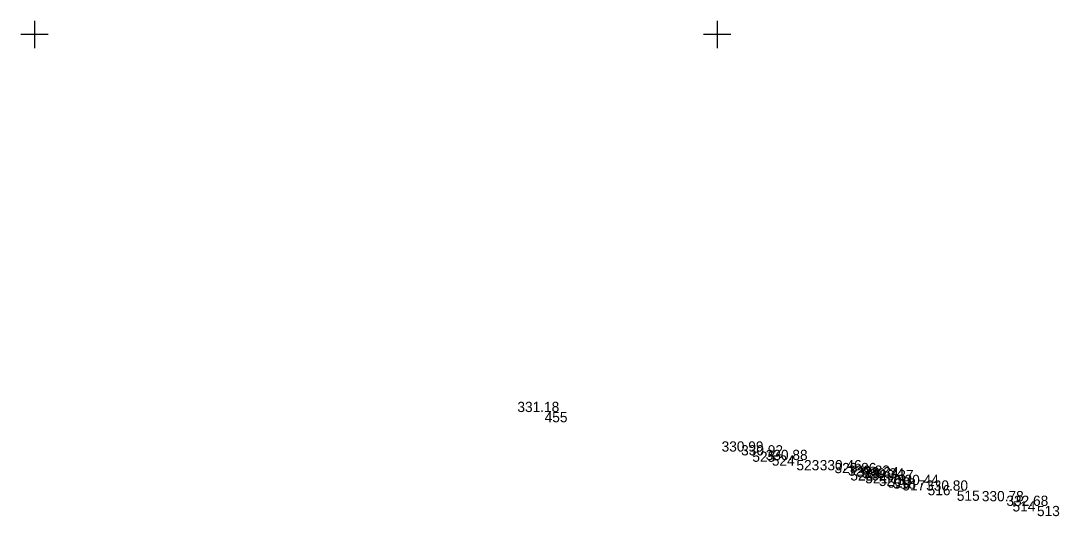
# Model space of a CAD drawing. Extents: x -718951 to -718443, y -1070201 to -1068444.
# Drawn here: x -718801 to -718724.9, y -1069435.3 to -1069399 of the extents above; entities that cross this region are included whole.
import ezdxf

# ---------------------------------------------------------------- set-up
doc = ezdxf.new("R2010")
doc.units = 0
for name, color, linetype in [('GEO_Body polohopis', 7, 'Continuous'), ('GEO_Hektarová síť', 7, 'Continuous'), ('GEO_Výšky bodů polohopis', 7, 'Continuous'), ('GEO_Čísla bodů polohopis', 7, 'Continuous')]:
    doc.layers.add(name, color=color, linetype=linetype)

msp = doc.modelspace()

# ---------------------------------------------------------------- linework, layer by layer
at = {"layer": 'GEO_Body polohopis'}
for p, q in [((-718762.63, -1069427.69), (-718762.63, -1069427.69)), ((-718747.42, -1069430.59), (-718747.42, -1069430.59)), ((-718745.99, -1069430.87), (-718745.99, -1069430.87)), ((-718744.19, -1069431.21), (-718744.19, -1069431.21)), ((-718740.24, -1069431.96), (-718740.24, -1069431.96)), ((-718739.15, -1069432.17), (-718739.15, -1069432.17)), ((-718738.15, -1069432.36), (-718738.15, -1069432.36)), ((-718737.52, -1069432.48), (-718737.52, -1069432.48)), ((-718737.11, -1069432.56), (-718737.11, -1069432.56)), ((-718736.43, -1069432.69), (-718736.43, -1069432.69)), ((-718734.58, -1069433.04), (-718734.58, -1069433.04)), ((-718732.44, -1069433.45), (-718732.44, -1069433.45)), ((-718728.36, -1069434.23), (-718728.36, -1069434.23)), ((-718726.57, -1069434.57), (-718726.57, -1069434.57))]:
    msp.add_line(p, q, dxfattribs=at)
at = {"layer": 'GEO_Hektarová síť'}
for points in [[(-718800, -1069399), (-718800, -1069400), (-718800, -1069401)], [(-718750, -1069399), (-718750, -1069400), (-718750, -1069401)], [(-718799, -1069400), (-718800, -1069400), (-718801, -1069400)], [(-718749, -1069400), (-718750, -1069400), (-718751, -1069400)]]:
    msp.add_lwpolyline(points, dxfattribs=at)

# ---------------------------------------------------------------- texts
at = {"layer": 'GEO_Výšky bodů polohopis'}
for s, p in [('331.18 ', (-718764.626, -1069427.69)), ('330.99 ', (-718749.669, -1069430.59)), ('330.92 ', (-718748.239, -1069430.87)), ('330.88 ', (-718746.439, -1069431.21)), ('330.46 ', (-718742.481, -1069431.96)), ('329.86 ', (-718741.402, -1069432.17)), ('329.82 ', (-718740.411, -1069432.36)), ('329.34 ', (-718739.769, -1069432.48)), ('329.34 ', (-718739.359, -1069432.56)), ('329.37 ', (-718738.679, -1069432.69)), ('330.44 ', (-718736.829, -1069433.04)), ('330.80 ', (-718734.689, -1069433.45)), ('330.78 ', (-718730.609, -1069434.23)), ('332.68 ', (-718728.811, -1069434.57))]:
    msp.add_text(s, height=0.75, dxfattribs=at).set_placement(p)
at = {"layer": 'GEO_Čísla bodů polohopis'}
for s, p in [('455', (-718762.63, -1069428.44)), ('525', (-718747.42, -1069431.34)), ('524', (-718745.99, -1069431.62)), ('523', (-718744.19, -1069431.96)), ('522', (-718740.24, -1069432.71)), ('521', (-718739.15, -1069432.92)), ('520', (-718738.15, -1069433.11)), ('519', (-718737.52, -1069433.23)), ('518', (-718737.11, -1069433.31)), ('517', (-718736.43, -1069433.44)), ('516', (-718734.58, -1069433.79)), ('515', (-718732.44, -1069434.2)), ('514', (-718728.36, -1069434.98)), ('513', (-718726.57, -1069435.32))]:
    msp.add_text(s, height=0.75, dxfattribs=at).set_placement(p)

doc.saveas('drawing.dxf')
